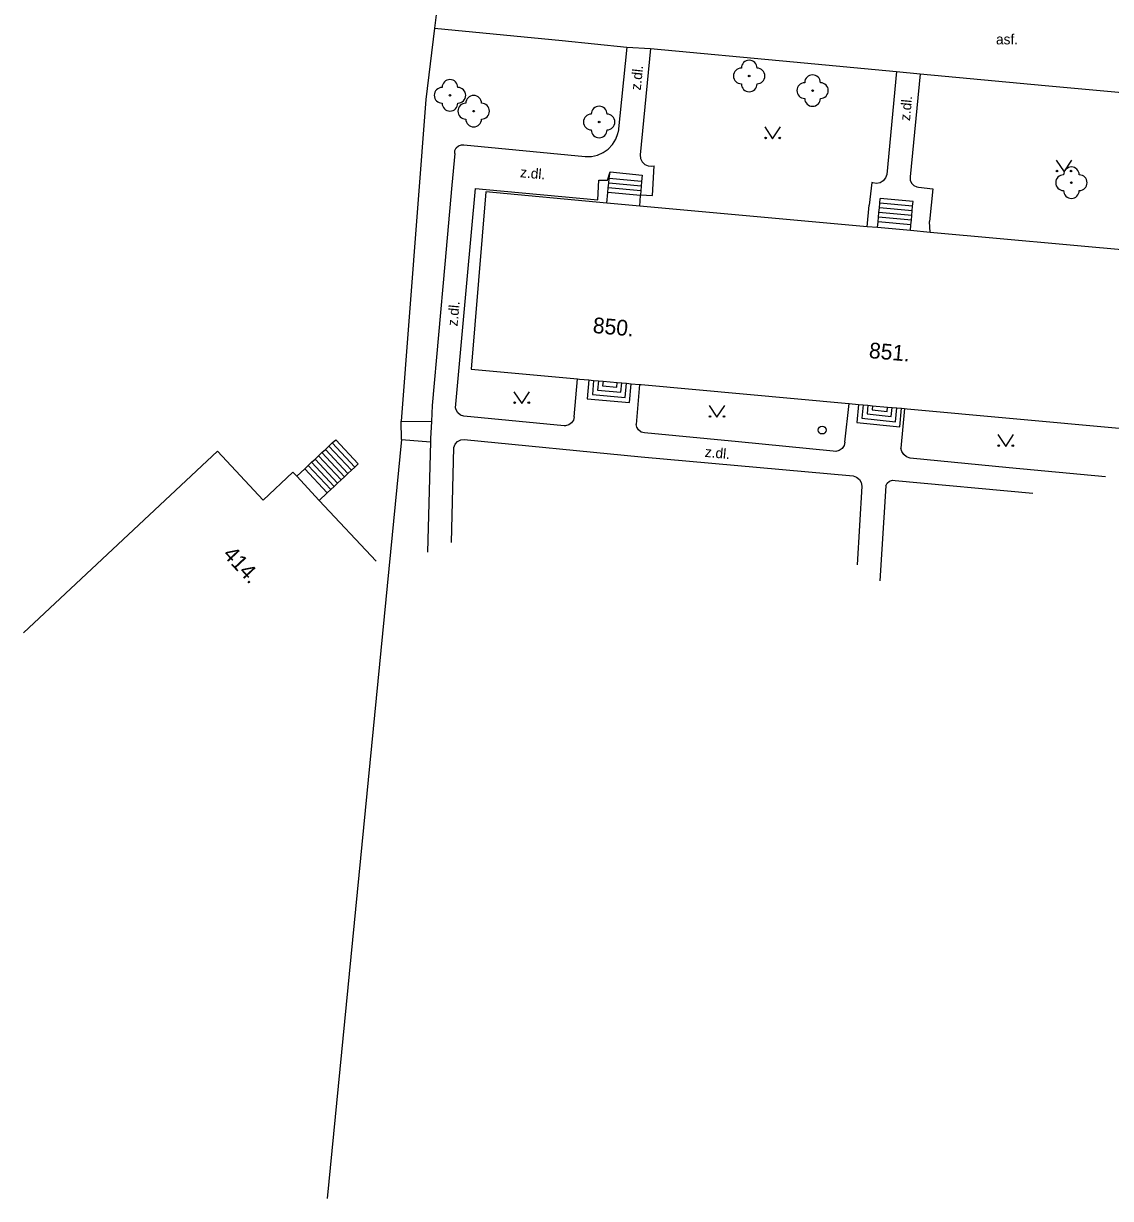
# Model space of a CAD drawing. Extents: x -538441 to -536770, y -1181008 to -1179809.
# Drawn here: x -537211.4 to -537142.3, y -1180924.1 to -1180849.4 of the extents above; entities that cross this region are included whole.
import ezdxf

# ---------------------------------------------------------------- set-up
doc = ezdxf.new("R2010")
doc.units = 0
for name, color, linetype in [('Vrstva 10', 7, 'Continuous'), ('Vrstva 11', 7, 'Continuous'), ('Vrstva 22', 7, 'Continuous'), ('Vrstva 28', 7, 'Continuous'), ('Vrstva 36', 7, 'Continuous'), ('Vrstva 40', 7, 'Continuous'), ('Vrstva 47', 7, 'Continuous'), ('Vrstva 5', 7, 'Continuous'), ('Vrstva 7', 7, 'Continuous'), ('Vrstva 8', 7, 'Continuous')]:
    doc.layers.add(name, color=color, linetype=linetype)

msp = doc.modelspace()

# ---------------------------------------------------------------- linework, layer by layer
at = {"layer": 'Vrstva 10'}
for p, q in [((-537185.241, -1180849.7), (-537177.118, -1180850.484)), ((-537177.118, -1180850.484), (-537173.002, -1180850.905)), ((-537173.002, -1180850.905), (-537171.511, -1180850.987)), ((-537171.511, -1180850.987), (-537162.419, -1180851.837)), ((-537162.419, -1180851.837), (-537155.867, -1180852.449)), ((-537155.867, -1180852.449), (-537154.358, -1180852.611)), ((-537154.358, -1180852.611), (-537146.401, -1180853.341)), ((-537146.401, -1180853.341), (-537138.685, -1180854.059))]:
    msp.add_line(p, q, dxfattribs=at)
at = {"layer": 'Vrstva 11'}
for p, q in [((-537173.002, -1180850.905), (-537173.561, -1180856.318)), ((-537171.511, -1180850.987), (-537172.159, -1180857.758)), ((-537155.867, -1180852.449), (-537156.48, -1180859.005)), ((-537154.358, -1180852.611), (-537154.995, -1180859.152)), ((-537183.367, -1180857.129), (-537175.66, -1180857.86)), ((-537183.947, -1180857.678), (-537184.134, -1180859.694)), ((-537184.134, -1180859.694), (-537184.576, -1180864.702)), ((-537172.124, -1180860.044), (-537174.191, -1180859.856)), ((-537172.097, -1180859.745), (-537174.164, -1180859.557)), ((-537172.07, -1180859.446), (-537174.137, -1180859.258)), ((-537157.435, -1180859.524), (-537157.606, -1180860.958)), ((-537183.174, -1180865.693), (-537182.642, -1180859.907)), ((-537182.642, -1180859.907), (-537181.951, -1180859.968)), ((-537181.951, -1180859.968), (-537174.862, -1180860.612)), ((-537172.149, -1180860.343), (-537174.218, -1180860.155)), ((-537154.811, -1180860.72), (-537156.9, -1180860.53)), ((-537157.726, -1180862.327), (-537157.606, -1180860.958)), ((-537154.865, -1180861.317), (-537156.954, -1180861.127)), ((-537154.838, -1180861.018), (-537156.927, -1180860.828)), ((-537154.946, -1180862.213), (-537157.035, -1180862.023)), ((-537154.919, -1180861.915), (-537157.008, -1180861.725)), ((-537154.892, -1180861.616), (-537156.981, -1180861.426)), ((-537153.726, -1180862.691), (-537153.765, -1180861.994)), ((-537184.576, -1180864.702), (-537185.393, -1180873.694)), ((-537183.91, -1180873.85), (-537183.174, -1180865.693)), ((-537176.36, -1180874.415), (-537176.14, -1180872.01)), ((-537172.2, -1180872.36), (-537172.423, -1180874.902)), ((-537159.143, -1180876.036), (-537158.878, -1180873.574)), ((-537155.344, -1180873.895), (-537155.585, -1180876.407)), ((-537187.36, -1180874.7), (-537185.439, -1180874.717)), ((-537176.989, -1180874.984), (-537183.372, -1180874.38)), ((-537165.902, -1180876.012), (-537171.894, -1180875.443)), ((-537191.962, -1180876.285), (-537190.528, -1180877.819)), ((-537191.743, -1180876.08), (-537190.309, -1180877.614)), ((-537191.524, -1180875.876), (-537190.09, -1180877.41)), ((-537187.35, -1180875.87), (-537185.494, -1180875.998)), ((-537185.494, -1180875.998), (-537185.684, -1180883.017)), ((-537185.488, -1180875.792), (-537185.494, -1180875.998)), ((-537183.366, -1180875.86), (-537172.094, -1180876.957)), ((-537159.883, -1180876.609), (-537165.902, -1180876.012)), ((-537192.619, -1180876.9), (-537191.185, -1180878.434)), ((-537192.4, -1180876.695), (-537190.966, -1180878.229)), ((-537192.181, -1180876.49), (-537190.747, -1180878.024)), ((-537184.163, -1180882.404), (-537184.009, -1180876.374)), ((-537172.094, -1180876.957), (-537158.616, -1180878.171)), ((-537193.496, -1180877.719), (-537192.062, -1180879.253)), ((-537193.277, -1180877.514), (-537191.843, -1180879.048)), ((-537193.058, -1180877.31), (-537191.624, -1180878.844)), ((-537192.838, -1180877.105), (-537191.404, -1180878.639)), ((-537148.707, -1180877.652), (-537154.995, -1180877.053)), ((-537142.566, -1180878.231), (-537148.707, -1180877.652)), ((-537155.948, -1180878.461), (-537147.186, -1180879.28)), ((-537158.068, -1180878.824), (-537158.361, -1180883.829)), ((-537156.546, -1180878.815), (-537156.933, -1180884.839))]:
    msp.add_line(p, q, dxfattribs=at)
for points in [[(-537175.66, -1180857.86), (-537175.264, -1180857.857), (-537174.878, -1180857.774), (-537174.515, -1180857.615), (-537174.192, -1180857.387), (-537173.921, -1180857.099), (-537173.714, -1180856.762), (-537173.578, -1180856.39), (-537173.561, -1180856.318)], [(-537183.947, -1180857.678), (-537183.939, -1180857.483), (-537183.855, -1180857.307), (-537183.707, -1180857.179), (-537183.521, -1180857.12), (-537183.367, -1180857.129)], [(-537172.159, -1180857.758), (-537172.133, -1180857.99), (-537172.03, -1180858.199), (-537171.863, -1180858.362), (-537171.651, -1180858.459), (-537171.419, -1180858.479), (-537171.27, -1180858.45)], [(-537174.862, -1180860.612), (-537174.797, -1180859.367), (-537174.243, -1180859.376), (-537174.063, -1180858.846), (-537172.035, -1180859.053), (-537172.07, -1180859.446), (-537172.097, -1180859.745), (-537172.124, -1180860.044), (-537172.147, -1180860.306), (-537171.386, -1180860.352), (-537171.27, -1180858.45)], [(-537174.279, -1180860.821), (-537174.218, -1180860.155), (-537174.191, -1180859.856), (-537174.164, -1180859.557), (-537174.137, -1180859.258), (-537174.063, -1180858.846)], [(-537156.48, -1180859.005), (-537156.56, -1180859.226), (-537156.709, -1180859.408), (-537156.91, -1180859.53), (-537157.14, -1180859.578), (-537157.373, -1180859.547), (-537157.435, -1180859.524)], [(-537154.995, -1180859.152), (-537154.991, -1180859.363), (-537154.91, -1180859.557), (-537154.763, -1180859.708), (-537154.57, -1180859.794), (-537154.465, -1180859.808)], [(-537154.465, -1180859.808), (-537153.56, -1180859.923), (-537153.765, -1180861.994)], [(-537172.19, -1180861.011), (-537172.149, -1180860.343), (-537172.147, -1180860.306)], [(-537157.069, -1180862.387), (-537157.035, -1180862.023), (-537157.008, -1180861.725), (-537156.981, -1180861.426), (-537156.954, -1180861.127), (-537156.927, -1180860.828), (-537156.9, -1180860.53)], [(-537154.98, -1180862.577), (-537154.946, -1180862.213), (-537154.919, -1180861.915), (-537154.892, -1180861.616), (-537154.865, -1180861.317), (-537154.838, -1180861.018), (-537154.811, -1180860.72)], [(-537175.421, -1180872.071), (-537175.53, -1180873.27), (-537172.84, -1180873.51), (-537172.731, -1180872.315)], [(-537175.122, -1180872.098), (-537175.204, -1180872.998), (-537173.112, -1180873.185), (-537173.03, -1180872.288)], [(-537174.823, -1180872.125), (-537174.878, -1180872.726), (-537173.383, -1180872.859), (-537173.329, -1180872.26)], [(-537174.525, -1180872.152), (-537174.552, -1180872.454), (-537173.655, -1180872.534), (-537173.627, -1180872.233)], [(-537185.393, -1180873.694), (-537185.439, -1180874.717), (-537185.488, -1180875.792)], [(-537183.372, -1180874.38), (-537183.585, -1180874.311), (-537183.76, -1180874.172), (-537183.875, -1180873.981), (-537183.91, -1180873.85)], [(-537158.286, -1180873.628), (-537158.39, -1180874.77), (-537155.65, -1180875.06), (-537155.542, -1180873.877)], [(-537157.987, -1180873.655), (-537158.064, -1180874.503), (-537155.921, -1180874.73), (-537155.841, -1180873.85)], [(-537157.688, -1180873.682), (-537157.739, -1180874.236), (-537156.192, -1180874.399), (-537156.14, -1180873.822)], [(-537157.39, -1180873.71), (-537157.413, -1180873.968), (-537156.463, -1180874.069), (-537156.438, -1180873.795)], [(-537176.36, -1180874.415), (-537176.409, -1180874.627), (-537176.531, -1180874.807), (-537176.709, -1180874.932), (-537176.92, -1180874.984), (-537176.989, -1180874.984)], [(-537171.894, -1180875.443), (-537172.101, -1180875.385), (-537172.272, -1180875.255), (-537172.385, -1180875.073), (-537172.423, -1180874.902)], [(-537194.007, -1180878.197), (-537193.496, -1180877.719), (-537193.277, -1180877.514), (-537193.058, -1180877.31), (-537192.838, -1180877.105), (-537192.619, -1180876.9), (-537192.4, -1180876.695), (-537192.181, -1180876.49), (-537191.962, -1180876.285), (-537191.743, -1180876.08), (-537191.524, -1180875.876)], [(-537184.009, -1180876.374), (-537183.925, -1180876.164), (-537183.773, -1180875.996), (-537183.573, -1180875.89), (-537183.366, -1180875.86)], [(-537159.143, -1180876.036), (-537159.195, -1180876.252), (-537159.319, -1180876.435), (-537159.5, -1180876.563), (-537159.715, -1180876.619), (-537159.883, -1180876.609)], [(-537154.995, -1180877.053), (-537155.22, -1180876.973), (-537155.406, -1180876.823), (-537155.533, -1180876.621), (-537155.585, -1180876.407)], [(-537192.573, -1180879.731), (-537192.062, -1180879.253), (-537191.843, -1180879.048), (-537191.624, -1180878.844), (-537191.404, -1180878.639), (-537191.185, -1180878.434), (-537190.966, -1180878.229), (-537190.747, -1180878.024), (-537190.528, -1180877.819), (-537190.309, -1180877.614), (-537190.09, -1180877.41)], [(-537158.616, -1180878.171), (-537158.401, -1180878.248), (-537158.225, -1180878.395), (-537158.109, -1180878.592), (-537158.068, -1180878.824)], [(-537156.546, -1180878.815), (-537156.462, -1180878.638), (-537156.314, -1180878.508), (-537156.127, -1180878.448), (-537155.948, -1180878.461)]]:
    msp.add_lwpolyline(points, dxfattribs=at)
at = {"layer": 'Vrstva 22'}
for centre in [(-537165.23, -1180852.74), (-537161.2, -1180853.67), (-537184.26, -1180853.97), (-537182.75, -1180854.98), (-537174.77, -1180855.67), (-537144.74, -1180859.53)]:
    msp.add_circle(centre, 0.05, dxfattribs=at)
for centre, start, end in [((-537165.73, -1180852.74), 90, 270), ((-537165.23, -1180852.24), 0, 180), ((-537164.73, -1180852.74), 270, 90), ((-537184.26, -1180853.47), 0, 180), ((-537161.2, -1180853.17), 0, 180), ((-537184.76, -1180853.97), 90, 270), ((-537183.76, -1180853.97), 270, 90), ((-537165.23, -1180853.24), 180, 0), ((-537161.7, -1180853.67), 90, 270), ((-537160.7, -1180853.67), 270, 90), ((-537184.26, -1180854.47), 180, 0), ((-537183.25, -1180854.98), 90, 270), ((-537182.75, -1180854.48), 0, 180), ((-537182.25, -1180854.98), 270, 90), ((-537161.2, -1180854.17), 180, 0), ((-537175.27, -1180855.67), 90, 270), ((-537174.77, -1180855.17), 0, 180), ((-537174.27, -1180855.67), 270, 90), ((-537182.75, -1180855.48), 180, 0), ((-537174.77, -1180856.17), 180, 0), ((-537145.24, -1180859.53), 90, 270), ((-537144.74, -1180859.03), 0, 180), ((-537144.24, -1180859.53), 270, 90), ((-537144.74, -1180860.03), 180, 0)]:
    msp.add_arc(centre, 0.5, start, end, dxfattribs=at)
at = {"layer": 'Vrstva 28'}
msp.add_circle((-537160.59, -1180875.26), 0.25, dxfattribs=at)
at = {"layer": 'Vrstva 36'}
for points in [[(-537164.238, -1180855.979), (-537163.738, -1180856.729), (-537163.238, -1180855.979)], [(-537145.711, -1180858.089), (-537145.211, -1180858.839), (-537144.711, -1180858.089)], [(-537180.196, -1180872.823), (-537179.696, -1180873.573), (-537179.196, -1180872.823)], [(-537167.778, -1180873.697), (-537167.278, -1180874.447), (-537166.778, -1180873.697)], [(-537149.414, -1180875.549), (-537148.914, -1180876.299), (-537148.414, -1180875.549)]]:
    msp.add_lwpolyline(points, dxfattribs=at)
for centre in [(-537164.188, -1180856.679), (-537163.289, -1180856.679), (-537145.661, -1180858.789), (-537144.762, -1180858.789), (-537180.146, -1180873.523), (-537179.247, -1180873.523), (-537167.728, -1180874.397), (-537166.829, -1180874.397), (-537149.364, -1180876.249), (-537148.465, -1180876.249)]:
    msp.add_circle(centre, 0.05, dxfattribs=at)
at = {"layer": 'Vrstva 5'}
for p, q in [((-537181.98, -1180860.12), (-537182.91, -1180871.39)), ((-537199.047, -1180876.612), (-537211.378, -1180888.145)), ((-537199.047, -1180876.612), (-537196.145, -1180879.717)), ((-537196.145, -1180879.717), (-537194.245, -1180877.941))]:
    msp.add_line(p, q, dxfattribs=at)
for points in [[(-537129.89, -1180864.86), (-537136.588, -1180864.25), (-537137.801, -1180864.14), (-537139.897, -1180863.949), (-537140.606, -1180863.884), (-537153.726, -1180862.691), (-537154.98, -1180862.577), (-537157.069, -1180862.387), (-537157.726, -1180862.327), (-537172.19, -1180861.011), (-537174.279, -1180860.821), (-537181.98, -1180860.12)], [(-537182.91, -1180871.39), (-537176.14, -1180872.01), (-537176.031, -1180872.015), (-537175.421, -1180872.071), (-537175.122, -1180872.098), (-537174.823, -1180872.125), (-537174.525, -1180872.152), (-537173.627, -1180872.233), (-537173.329, -1180872.26), (-537173.03, -1180872.288), (-537172.731, -1180872.315), (-537172.2, -1180872.36), (-537172.101, -1180872.372), (-537158.901, -1180873.572), (-537158.878, -1180873.574), (-537158.286, -1180873.628), (-537157.987, -1180873.655), (-537157.688, -1180873.682), (-537157.39, -1180873.71), (-537156.438, -1180873.795), (-537156.14, -1180873.822), (-537155.841, -1180873.85), (-537155.542, -1180873.877), (-537155.344, -1180873.895), (-537155.195, -1180873.909), (-537141.71, -1180875.134)], [(-537188.954, -1180883.603), (-537192.573, -1180879.731), (-537194.007, -1180878.197), (-537194.245, -1180877.941)]]:
    msp.add_lwpolyline(points, dxfattribs=at)
at = {"layer": 'Vrstva 7'}
for p, q in [((-537185.8, -1180854.24), (-537187.36, -1180874.7)), ((-537187.35, -1180875.87), (-537192.07, -1180924.13))]:
    msp.add_line(p, q, dxfattribs=at)
msp.add_lwpolyline([(-537183.6, -1180836.36), (-537184.737, -1180845.605), (-537185.241, -1180849.7), (-537185.8, -1180854.24)], dxfattribs=at)
at = {"layer": 'Vrstva 8'}
msp.add_line((-537187.35, -1180875.87), (-537187.36, -1180874.7), dxfattribs=at)

# ---------------------------------------------------------------- texts
at = {"layer": 'Vrstva 40'}
msp.add_text('asf.', height=0.65, dxfattribs=at).set_placement((-537149.536, -1180850.733))
for rotation, p in [(84.10397, (-537172.132, -1180853.677)), (84.65825, (-537155.008, -1180855.617)), (354.58177, (-537179.817, -1180859.176)), (84.80844, (-537183.783, -1180868.678)), (354.57546, (-537168.071, -1180876.961))]:
    msp.add_text('z.dl.', height=0.65, rotation=rotation, dxfattribs=at).set_placement(p)
at = {"layer": 'Vrstva 47'}
for s, rotation, p in [('850.', 354.80755, (-537175.203, -1180869.078)), ('851.', 354.80755, (-537157.644, -1180870.674)), ('414.', 313.06002, (-537198.753, -1180883.214))]:
    msp.add_text(s, height=1, rotation=rotation, dxfattribs=at).set_placement(p)

doc.saveas('drawing.dxf')
